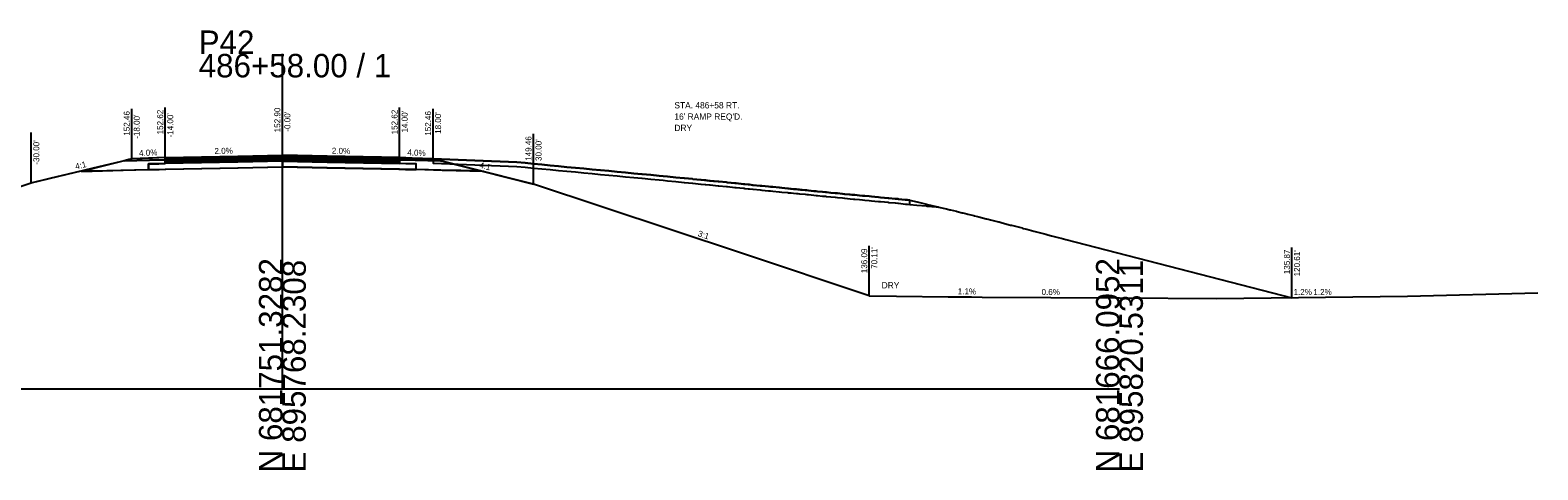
# Model space of a CAD drawing. Extents: x -26 to 4403, y -13 to 9578.
# Drawn here: x 3069.9 to 3250, y 8990.3 to 9042.8 of the extents above; entities that cross this region are included whole.
import ezdxf

# ---------------------------------------------------------------- set-up
doc = ezdxf.new("R2010")
doc.units = 0
for name, color, linetype in [('ASPHALT_19MM1', 7, 'Continuous'), ('ASPHALT_19MM2', 7, 'Continuous'), ('ASPHALT_9_5MM1', 7, 'Continuous'), ('CONST_LV3', 7, 'Continuous'), ('CONST_PROF_LV1', 7, 'Continuous'), ('Default', 7, 'Continuous'), ('DTM CONTOURS_MAJOR', 7, 'Continuous'), ('DTM_CONTOURS_MINOR', 7, 'Continuous'), ('DTM_P_FINISHED_GRADE', 7, 'Continuous'), ('DTM_X_BOUNDARY', 7, 'Continuous'), ('DTM_X_GROUND', 7, 'Continuous'), ('X_PROFILES_1', 7, 'Continuous'), ('XS_CELL', 7, 'Continuous'), ('XS_P_ASPHALT', 7, 'Continuous'), ('XS_P_CRUSHED_STONE', 7, 'Continuous'), ('XS_P_DR_ASPHALT', 7, 'Continuous'), ('XS_P_DR_ASPHALT_B', 7, 'Continuous'), ('XS_P_DR_GRAVEL', 7, 'Continuous'), ('XS_P_DRAINAGE', 7, 'Continuous'), ('XS_P_GROUND', 7, 'Continuous'), ('XS_P_SHOULDER', 7, 'Continuous'), ('XS_P_SUBGRADE_GRANULAR', 7, 'Continuous'), ('XS_P_TX_CLEARZONE', 7, 'Continuous'), ('XS_P_TX_FS_BS', 7, 'Continuous')]:
    doc.layers.add(name, color=color, linetype=linetype)

msp = doc.modelspace()

# ---------------------------------------------------------------- linework, layer by layer
at = {"layer": 'ASPHALT_19MM1'}
for points in [[(3094.67, 9027.5), (3100, 9027.61), (3100, 9027.54), (3100, 9027.42), (3094.67, 9027.32), (3086, 9027.14), (3086, 9027.26), (3086, 9027.33), (3094.67, 9027.5)], [(3105.33, 9027.5), (3100, 9027.61), (3100, 9027.54), (3100, 9027.42), (3105.33, 9027.32), (3114, 9027.14), (3114, 9027.26), (3114, 9027.33), (3105.33, 9027.5)]]:
    msp.add_lwpolyline(points, dxfattribs=at)
at = {"layer": 'ASPHALT_19MM2'}
for points in [[(3094.67, 9027.32), (3100, 9027.42), (3100, 9027.33), (3100, 9027.17), (3094.67, 9027.07), (3086, 9026.89), (3086, 9027.05), (3086, 9027.14), (3094.67, 9027.32)], [(3105.33, 9027.32), (3100, 9027.42), (3100, 9027.33), (3100, 9027.17), (3105.33, 9027.07), (3114, 9026.89), (3114, 9027.05), (3114, 9027.14), (3105.33, 9027.32)]]:
    msp.add_lwpolyline(points, dxfattribs=at)
at = {"layer": 'ASPHALT_9_5MM1'}
for points in [[(3094.67, 9027.79), (3100, 9027.9), (3100, 9027.85), (3100, 9027.78), (3094.67, 9027.67), (3086, 9027.5), (3086, 9027.57), (3086, 9027.62), (3094.67, 9027.79)], [(3105.33, 9027.79), (3100, 9027.9), (3100, 9027.85), (3100, 9027.78), (3105.33, 9027.67), (3114, 9027.5), (3114, 9027.57), (3114, 9027.62), (3105.33, 9027.79)]]:
    msp.add_lwpolyline(points, dxfattribs=at)
at = {"layer": 'CONST_LV3'}
for points in [[(3114, 9027.62), (3115, 9027.58), (3116, 9027.54), (3117, 9027.5), (3118, 9027.46), (3119, 9027.42), (3120, 9027.38), (3121, 9027.34), (3122, 9027.3), (3123, 9027.26), (3124, 9027.22), (3125, 9027.18), (3126, 9027.14), (3127, 9027.1), (3128, 9027.06), (3129, 9026.97), (3130, 9026.87), (3131, 9026.78), (3132, 9026.68), (3133, 9026.59), (3134, 9026.49), (3135, 9026.4), (3136, 9026.3), (3137, 9026.21), (3138, 9026.11), (3139, 9026.02), (3140, 9025.92), (3141, 9025.83), (3142, 9025.73), (3142.94, 9025.64), (3143, 9025.64), (3144, 9025.54), (3144, 9025.54), (3144, 9025.54), (3145, 9025.45), (3145, 9025.45), (3145, 9025.44), (3146, 9025.35), (3146, 9025.35), (3146.5, 9025.3), (3146.5, 9025.3), (3147, 9025.25), (3147.01, 9025.25), (3147.01, 9025.25), (3147.99, 9025.15), (3148.01, 9025.15), (3148.02, 9025.15), (3148.99, 9025.06), (3149.02, 9025.05), (3149.03, 9025.05), (3149.98, 9024.96), (3150.03, 9024.95), (3150.04, 9024.95), (3150.09, 9024.95), (3151.04, 9024.85), (3151.04, 9024.85), (3151.51, 9024.81), (3151.59, 9024.8), (3152.05, 9024.76), (3152.06, 9024.75), (3152.14, 9024.75), (3153.06, 9024.66), (3153.1, 9024.65), (3153.17, 9024.65), (3154.07, 9024.56), (3154.13, 9024.55), (3154.2, 9024.54), (3155.07, 9024.46), (3155.17, 9024.45), (3155.23, 9024.44), (3156.08, 9024.36), (3156.21, 9024.34), (3156.26, 9024.34), (3156.67, 9024.3), (3156.85, 9024.28), (3157.26, 9024.24), (3157.29, 9024.24), (3158.08, 9024.16), (3158.32, 9024.13), (3158.32, 9024.13), (3158.58, 9024.11), (3159.35, 9024.03), (3159.39, 9024.03), (3159.65, 9024), (3160.39, 9023.93), (3160.45, 9023.92), (3160.72, 9023.9), (3161.42, 9023.83), (3161.57, 9023.81), (3161.9, 9023.78), (3162.13, 9023.76), (3162.45, 9023.73), (3162.67, 9023.71), (3162.86, 9023.69), (3163.48, 9023.62), (3163.75, 9023.6), (3163.94, 9023.58), (3164.51, 9023.52), (3164.88, 9023.49), (3165.01, 9023.48), (3165.53, 9023.42), (3166.05, 9023.37), (3166.08, 9023.37), (3166.69, 9023.31), (3167.16, 9023.26), (3167.21, 9023.26), (3167.42, 9023.24), (3168.03, 9023.18), (3168.23, 9023.16), (3168.38, 9023.15), (3168.96, 9023.09), (3169.31, 9023.06), (3169.57, 9023.04), (3170.09, 9022.99), (3170.38, 9022.96), (3170.77, 9022.92), (3171.23, 9022.88), (3171.45, 9022.86), (3171.94, 9022.81), (3172.37, 9022.77), (3172.53, 9022.76), (3173.24, 9022.69), (3173.51, 9022.67), (3173.55, 9022.66), (3174.42, 9022.57), (3174.43, 9022.57), (3174.65, 9022.56), (3174.67, 9022.56), (3174.94, 9022.53)], [(3070, 9024.61), (3072.24, 9025.14), (3075.95, 9026.02)], [(3123.72, 9026.03), (3130, 9024.46)]]:
    msp.add_lwpolyline(points, dxfattribs=at)
at = {"layer": 'Default'}
for points in [[(3094.67, 9027.67), (3100, 9027.78), (3100, 9027.71), (3100, 9027.61), (3094.67, 9027.5), (3086, 9027.33), (3086, 9027.43), (3086, 9027.5), (3094.67, 9027.67)], [(3105.33, 9027.67), (3100, 9027.78), (3100, 9027.71), (3100, 9027.61), (3105.33, 9027.5), (3114, 9027.33), (3114, 9027.43), (3114, 9027.5), (3105.33, 9027.67)]]:
    msp.add_lwpolyline(points, dxfattribs=at)
at = {"layer": 'DTM_P_FINISHED_GRADE'}
for points in [[(3114, 9027.62), (3115, 9027.58), (3116, 9027.54), (3117, 9027.5), (3118, 9027.46)], [(3118, 9027.46), (3119, 9027.42), (3120, 9027.38), (3121, 9027.34), (3122, 9027.3), (3123, 9027.26), (3124, 9027.22), (3125, 9027.18), (3126, 9027.14), (3127, 9027.1), (3128, 9027.06), (3129, 9026.97), (3130, 9026.87), (3131, 9026.78), (3132, 9026.68), (3133, 9026.59), (3134, 9026.49), (3135, 9026.4), (3136, 9026.3), (3137, 9026.21), (3138, 9026.11), (3139, 9026.02), (3140, 9025.92), (3141, 9025.83), (3142, 9025.73), (3142.94, 9025.64), (3143, 9025.64), (3144, 9025.54), (3144, 9025.54), (3144, 9025.54), (3145, 9025.45), (3145, 9025.45), (3145.5, 9025.4), (3145.5, 9025.4), (3146, 9025.35), (3146, 9025.35), (3146.01, 9025.35), (3147, 9025.25), (3147.01, 9025.25), (3147.01, 9025.25), (3147.99, 9025.15), (3148.01, 9025.15), (3148.02, 9025.15), (3148.99, 9025.06), (3149.02, 9025.05), (3149.03, 9025.05), (3149.98, 9024.96), (3150.03, 9024.95), (3150.04, 9024.95), (3150.51, 9024.91), (3150.57, 9024.9), (3151.04, 9024.85), (3151.04, 9024.85), (3151.11, 9024.85), (3152.05, 9024.76), (3152.06, 9024.75), (3152.14, 9024.75), (3153.06, 9024.66), (3153.1, 9024.65), (3153.17, 9024.65), (3154.07, 9024.56), (3154.13, 9024.55), (3154.2, 9024.54), (3155.07, 9024.46), (3155.17, 9024.45), (3155.23, 9024.44), (3155.66, 9024.4), (3155.79, 9024.39), (3156.21, 9024.34), (3156.26, 9024.34), (3157.08, 9024.26), (3157.26, 9024.24), (3157.29, 9024.24), (3158.08, 9024.16), (3158.32, 9024.13), (3158.32, 9024.13), (3158.58, 9024.11), (3159.35, 9024.03), (3159.39, 9024.03), (3159.65, 9024), (3160.39, 9023.93), (3160.45, 9023.92), (3160.8, 9023.89), (3161.07, 9023.86), (3161.42, 9023.83), (3161.57, 9023.81), (3161.79, 9023.79), (3162.45, 9023.73), (3162.67, 9023.71), (3162.86, 9023.69), (3163.48, 9023.62), (3163.75, 9023.6), (3163.94, 9023.58), (3164.51, 9023.52), (3164.88, 9023.49), (3165.01, 9023.48), (3165.53, 9023.42), (3166.05, 9023.37), (3166.08, 9023.37), (3166.33, 9023.35), (3166.93, 9023.29), (3167.16, 9023.26), (3167.21, 9023.26), (3167.83, 9023.2), (3168.23, 9023.16), (3168.38, 9023.15), (3168.96, 9023.09), (3169.31, 9023.06), (3169.57, 9023.04), (3170.09, 9022.99), (3170.38, 9022.96), (3170.77, 9022.92), (3171.23, 9022.88), (3171.45, 9022.86), (3171.94, 9022.81), (3172.37, 9022.77), (3172.45, 9022.76), (3173.19, 9022.69), (3173.24, 9022.69), (3173.51, 9022.67), (3173.6, 9022.66), (3174.43, 9022.57), (3174.65, 9022.56), (3174.67, 9022.56), (3174.94, 9022.53)]]:
    msp.add_lwpolyline(points, dxfattribs=at)
at = {"layer": 'DTM_X_GROUND'}
for points in [[(3200, 9010.84), (3211.61, 9010.77), (3234.42, 9011.04), (3249.98, 9011.47)], [(3170.11, 9011.09), (3173.36, 9011.06), (3179.52, 9010.99), (3182.34, 9010.96), (3183.61, 9010.95), (3200, 9010.84)]]:
    msp.add_lwpolyline(points, dxfattribs=at)
at = {"layer": 'XS_CELL'}
for p, q in [((3100, 9000), (3100, 9040)), ((3000, 9000), (3100, 9000)), ((3100, 9000), (3200, 9000))]:
    msp.add_line(p, q, dxfattribs=at)
at = {"layer": 'XS_P_ASPHALT'}
msp.add_lwpolyline([(3094.67, 9027.79), (3100, 9027.9), (3105.33, 9027.79), (3114, 9027.62), (3114, 9027.34), (3114, 9026.89), (3105.33, 9027.07), (3100, 9027.17), (3094.67, 9027.07), (3086, 9026.89), (3086, 9027.34), (3086, 9027.62), (3094.67, 9027.79)], dxfattribs=at)
at = {"layer": 'XS_P_CRUSHED_STONE'}
for points in [[(3084.48, 9027.56), (3082, 9027.46), (3081.66, 9027.38), (3081.11, 9027.24), (3084.14, 9027.29), (3086, 9027.33), (3086, 9027.51), (3086, 9027.62), (3084.48, 9027.56)], [(3115.52, 9027.56), (3114, 9027.62), (3114, 9027.51), (3114, 9027.33), (3115.86, 9027.29), (3118.89, 9027.24), (3118.34, 9027.38), (3118, 9027.46), (3115.52, 9027.56)], [(3085.29, 9026.21), (3086.08, 9026.23), (3094.7, 9026.4), (3100, 9026.51), (3100, 9026.92), (3100, 9027.17), (3094.67, 9027.07), (3086, 9026.89), (3085.24, 9026.88), (3084.01, 9026.86), (3084.01, 9026.61), (3084, 9026.19), (3085.29, 9026.21)], [(3114.71, 9026.21), (3116, 9026.19), (3115.99, 9026.61), (3115.99, 9026.86), (3114.76, 9026.88), (3114, 9026.89), (3105.33, 9027.07), (3100, 9027.17), (3100, 9026.92), (3100, 9026.51), (3105.3, 9026.4), (3113.92, 9026.23), (3114.71, 9026.21)]]:
    msp.add_lwpolyline(points, dxfattribs=at)
at = {"layer": 'XS_P_DR_ASPHALT'}
msp.add_lwpolyline([(3116, 9027.54), (3117, 9027.5), (3118, 9027.46), (3118, 9027.34), (3117, 9027.38), (3116, 9027.42), (3115, 9027.46), (3114, 9027.5), (3114, 9027.62), (3115, 9027.58), (3116, 9027.54)], dxfattribs=at)
at = {"layer": 'XS_P_DR_ASPHALT_B'}
msp.add_lwpolyline([(3116, 9027.42), (3117, 9027.38), (3118, 9027.34), (3118, 9027.21), (3117, 9027.25), (3116, 9027.29), (3115, 9027.33), (3114, 9027.37), (3114, 9027.5), (3115, 9027.46), (3116, 9027.42)], dxfattribs=at)
at = {"layer": 'XS_P_DR_GRAVEL'}
for points in [[(3122, 9027.3), (3121, 9027.34), (3120, 9027.38), (3119, 9027.42), (3118, 9027.46), (3118, 9026.96), (3119, 9026.92), (3120, 9026.88), (3121, 9026.84), (3122, 9026.8), (3123, 9026.76), (3124, 9026.72), (3125, 9026.68), (3126, 9026.64), (3127, 9026.6), (3128, 9026.56), (3129, 9026.47), (3130, 9026.37), (3131, 9026.28), (3132, 9026.18), (3133, 9026.09), (3134, 9025.99), (3135, 9025.9), (3136, 9025.8), (3137, 9025.71), (3138, 9025.61), (3139, 9025.52), (3140, 9025.42), (3141, 9025.33), (3142, 9025.23), (3142.94, 9025.14), (3142.94, 9025.14), (3143, 9025.14), (3143, 9025.14), (3143, 9025.14), (3144, 9025.04), (3144, 9025.04), (3144, 9025.04), (3145, 9024.95), (3145, 9024.95), (3145.5, 9024.9), (3145.5, 9024.9), (3146, 9024.85), (3146, 9024.85), (3146.01, 9024.85), (3147, 9024.75), (3147.01, 9024.75), (3147.01, 9024.75), (3147.99, 9024.65), (3148.01, 9024.65), (3148.02, 9024.65), (3148.99, 9024.56), (3149.02, 9024.55), (3149.03, 9024.55), (3149.98, 9024.46), (3150.03, 9024.45), (3150.04, 9024.45), (3150.51, 9024.41), (3150.57, 9024.4), (3151.04, 9024.35), (3151.04, 9024.35), (3151.11, 9024.35), (3152.05, 9024.26), (3152.06, 9024.25), (3152.14, 9024.25), (3153.06, 9024.16), (3153.1, 9024.15), (3153.17, 9024.15), (3154.07, 9024.06), (3154.13, 9024.05), (3154.2, 9024.04), (3155.07, 9023.96), (3155.17, 9023.95), (3155.23, 9023.94), (3155.66, 9023.9), (3155.79, 9023.89), (3156.21, 9023.84), (3156.26, 9023.84), (3157.08, 9023.76), (3157.26, 9023.74), (3157.29, 9023.74), (3158.08, 9023.66), (3158.32, 9023.63), (3158.32, 9023.63), (3158.58, 9023.61), (3159.35, 9023.53), (3159.39, 9023.53), (3159.65, 9023.5), (3160.39, 9023.43), (3160.45, 9023.42), (3160.8, 9023.39), (3161.07, 9023.36), (3161.42, 9023.33), (3161.57, 9023.31), (3161.79, 9023.29), (3162.45, 9023.23), (3162.67, 9023.21), (3162.86, 9023.19), (3163.48, 9023.12), (3163.75, 9023.1), (3163.94, 9023.08), (3164.51, 9023.02), (3164.88, 9022.99), (3165.01, 9022.98), (3165.53, 9022.92), (3166.05, 9022.87), (3166.08, 9022.87), (3166.33, 9022.85), (3166.93, 9022.79), (3167.16, 9022.76), (3167.21, 9022.76), (3167.83, 9022.7), (3168.23, 9022.66), (3168.38, 9022.65), (3168.96, 9022.59), (3169.31, 9022.56), (3169.57, 9022.54), (3170.09, 9022.49), (3170.38, 9022.46), (3170.77, 9022.42), (3171.23, 9022.38), (3171.45, 9022.36), (3171.94, 9022.31), (3172.37, 9022.27), (3172.45, 9022.26), (3173.19, 9022.19), (3173.24, 9022.19), (3173.51, 9022.17), (3173.6, 9022.16), (3174.43, 9022.07), (3174.65, 9022.06), (3174.67, 9022.06), (3174.94, 9022.03), (3174.94, 9022.53), (3174.67, 9022.56), (3174.65, 9022.56), (3174.43, 9022.57), (3173.6, 9022.66), (3173.51, 9022.67), (3173.24, 9022.69), (3173.19, 9022.69), (3172.45, 9022.76), (3172.37, 9022.77), (3171.94, 9022.81), (3171.45, 9022.86), (3171.23, 9022.88), (3170.77, 9022.92), (3170.38, 9022.96), (3170.09, 9022.99), (3169.57, 9023.04), (3169.31, 9023.06), (3168.96, 9023.09), (3168.38, 9023.15), (3168.23, 9023.16), (3167.83, 9023.2), (3167.21, 9023.26), (3167.16, 9023.26), (3166.93, 9023.29), (3166.33, 9023.35), (3166.08, 9023.37), (3166.05, 9023.37), (3165.53, 9023.42), (3165.01, 9023.48), (3164.88, 9023.49), (3164.51, 9023.52), (3163.94, 9023.58), (3163.75, 9023.6), (3163.48, 9023.62), (3162.86, 9023.69), (3162.67, 9023.71), (3162.45, 9023.73), (3161.79, 9023.79), (3161.57, 9023.81), (3161.42, 9023.83), (3161.07, 9023.86), (3160.8, 9023.89), (3160.45, 9023.92), (3160.39, 9023.93), (3159.65, 9024), (3159.39, 9024.03), (3159.35, 9024.03), (3158.58, 9024.11), (3158.32, 9024.13), (3158.32, 9024.13), (3158.08, 9024.16), (3157.29, 9024.24), (3157.26, 9024.24), (3157.08, 9024.26), (3156.26, 9024.34), (3156.21, 9024.34), (3155.79, 9024.39), (3155.66, 9024.4), (3155.23, 9024.44), (3155.17, 9024.45), (3155.07, 9024.46), (3154.2, 9024.54), (3154.13, 9024.55), (3154.07, 9024.56), (3153.17, 9024.65), (3153.1, 9024.65), (3153.06, 9024.66), (3152.14, 9024.75), (3152.06, 9024.75), (3152.05, 9024.76), (3151.11, 9024.85), (3151.04, 9024.85), (3151.04, 9024.85), (3150.57, 9024.9), (3150.51, 9024.91), (3150.04, 9024.95), (3150.03, 9024.95), (3149.98, 9024.96), (3149.03, 9025.05), (3149.02, 9025.05), (3148.99, 9025.06), (3148.02, 9025.15), (3148.01, 9025.15), (3147.99, 9025.15), (3147.01, 9025.25), (3147.01, 9025.25), (3147, 9025.25), (3146.01, 9025.35), (3146, 9025.35), (3146, 9025.35), (3145.5, 9025.4), (3145.5, 9025.4), (3145, 9025.45), (3145, 9025.45), (3144, 9025.54), (3144, 9025.54), (3144, 9025.54), (3143, 9025.64), (3143, 9025.64), (3143, 9025.64), (3142.94, 9025.64), (3142.94, 9025.64), (3142, 9025.73), (3141, 9025.83), (3140, 9025.92), (3139, 9026.02), (3138, 9026.11), (3137, 9026.21), (3136, 9026.3), (3135, 9026.4), (3134, 9026.49), (3133, 9026.59), (3132, 9026.68), (3131, 9026.78), (3130, 9026.87), (3129, 9026.97), (3128, 9027.06), (3127, 9027.1), (3126, 9027.14), (3125, 9027.18), (3124, 9027.22), (3123, 9027.26), (3122, 9027.3)], [(3174.94, 9022.03), (3175.79, 9021.95), (3175.8, 9021.95), (3176.94, 9021.84), (3177.03, 9021.83), (3178.12, 9021.73), (3178.37, 9021.71), (3178.42, 9021.7)]]:
    msp.add_lwpolyline(points, dxfattribs=at)
at = {"layer": 'XS_P_GROUND'}
for points in [[(3042.68, 9015.51), (3053.11, 9018.98), (3070, 9024.61), (3077.43, 9026.39), (3082, 9027.46)], [(3170.11, 9011.09), (3154.85, 9016.18), (3130, 9024.46), (3122.57, 9026.32), (3118, 9027.46)], [(3174.94, 9022.53), (3175.79, 9022.33), (3175.8, 9022.33), (3175.8, 9022.33), (3175.82, 9022.33), (3176.94, 9022.06), (3176.95, 9022.06), (3177.03, 9022.04), (3177.08, 9022.03), (3178.12, 9021.78), (3178.13, 9021.78), (3178.37, 9021.72), (3178.44, 9021.7), (3179.31, 9021.49), (3179.35, 9021.48), (3179.73, 9021.39), (3179.81, 9021.37), (3180.53, 9021.2), (3180.61, 9021.18), (3181.2, 9021.03), (3181.28, 9021.02), (3181.77, 9020.89), (3181.9, 9020.86), (3182.62, 9020.68), (3182.69, 9020.66), (3183.04, 9020.58), (3183.22, 9020.53), (3184.08, 9020.31), (3184.13, 9020.3), (3184.33, 9020.26), (3184.59, 9020.19), (3185.56, 9019.94), (3185.62, 9019.92), (3185.64, 9019.92), (3185.97, 9019.84), (3186.98, 9019.56), (3187.01, 9019.56), (3187.09, 9019.54), (3187.44, 9019.46), (3188.36, 9019.21), (3188.42, 9019.19), (3188.55, 9019.16), (3188.93, 9019.06), (3189.76, 9018.84), (3189.92, 9018.8), (3190.25, 9018.71), (3190.58, 9018.63), (3191.2, 9018.46), (3191.45, 9018.4), (3191.89, 9018.28), (3192.19, 9018.2), (3192.67, 9018.07), (3193.04, 9017.97), (3193.58, 9017.82), (3220.61, 9010.87)]]:
    msp.add_lwpolyline(points, dxfattribs=at)
at = {"layer": 'XS_P_SHOULDER'}
for points in [[(3086, 9027.62), (3082, 9027.46)], [(3114, 9027.62), (3118, 9027.46)]]:
    msp.add_lwpolyline(points, dxfattribs=at)
at = {"layer": 'XS_P_SUBGRADE_GRANULAR'}
for points in [[(3075.95, 9026.02), (3079.04, 9026.09), (3084, 9026.19), (3085.24, 9026.21), (3086, 9026.23)], [(3086, 9027.16), (3086, 9027.33), (3084.14, 9027.29), (3081.11, 9027.24), (3079.18, 9026.76), (3076.05, 9025.97), (3080.98, 9026.1), (3084, 9026.19), (3084.01, 9026.61), (3084.01, 9026.86), (3085.24, 9026.88), (3086, 9026.89), (3086, 9027.16)], [(3086, 9026.23), (3094.67, 9026.4), (3100, 9026.51)], [(3114, 9026.23), (3105.33, 9026.4), (3100, 9026.51)], [(3114, 9027.16), (3114, 9027.33), (3115.86, 9027.29), (3118.89, 9027.24), (3120.86, 9026.75), (3124.06, 9025.95), (3119.07, 9026.09), (3116, 9026.19), (3115.99, 9026.61), (3115.99, 9026.86), (3114.76, 9026.88), (3114, 9026.89), (3114, 9027.16)], [(3123.72, 9026.03), (3118.94, 9026.13), (3116, 9026.19), (3114.76, 9026.21), (3114, 9026.23)]]:
    msp.add_lwpolyline(points, dxfattribs=at)
at = {"layer": 'XS_P_TX_CLEARZONE'}
for p, q in [((3082, 9027.46), (3082, 9033.46)), ((3086, 9027.62), (3086, 9033.62)), ((3100, 9027.9), (3100, 9033.9)), ((3114, 9027.62), (3114, 9033.62)), ((3118, 9027.46), (3118, 9033.46)), ((3070, 9024.61), (3070, 9030.61)), ((3070, 9024.61), (3070, 9030.61)), ((3130, 9024.46), (3130, 9030.46)), ((3130, 9024.46), (3130, 9030.46)), ((3170.11, 9011.09), (3170.11, 9017.09)), ((3170.11, 9011.09), (3170.11, 9017.09)), ((3220.61, 9010.87), (3220.61, 9016.87))]:
    msp.add_line(p, q, dxfattribs=at)

# ---------------------------------------------------------------- texts
at = {"layer": 'CONST_PROF_LV1'}
for p in [(3069.96, 9024.55), (3129.96, 9024.4)]:
    msp.add_text('X', height=0.12, dxfattribs=at).set_placement(p)
at = {"layer": 'Default'}
for p in [(3069.96, 9024.55), (3129.96, 9024.4)]:
    msp.add_text('X', height=0.12, dxfattribs=at).set_placement(p)
at = {"layer": 'DTM CONTOURS_MAJOR'}
for p in [(3085.96, 9027.56), (3099.96, 9027.84), (3113.96, 9027.56)]:
    msp.add_text('X', height=0.12, dxfattribs=at).set_placement(p)
at = {"layer": 'DTM_CONTOURS_MINOR'}
msp.add_text('X', height=0.12, dxfattribs=at).set_placement((3170.07, 9011.03))
at = {"layer": 'DTM_X_BOUNDARY'}
for p in [(3081.96, 9027.4), (3117.96, 9027.4)]:
    msp.add_text('X', height=0.12, dxfattribs=at).set_placement(p)
at = {"layer": 'X_PROFILES_1'}
for p in [(3170.07, 9011.03), (3220.57, 9010.81)]:
    msp.add_text('X', height=0.12, dxfattribs=at).set_placement(p)
at = {"layer": 'XS_CELL'}
for s, p in [('P42', (3090, 9040)), ('486+58.00 / 1', (3090, 9037.2))]:
    msp.add_text(s, height=2.8, dxfattribs=at).set_placement(p)
for s, p in [('N 681751.3282', (3100, 8990)), ('E 895768.2308', (3102.8, 8990)), ('N 681666.0952', (3200, 8990)), ('E 895820.5311', (3202.8, 8990))]:
    msp.add_text(s, height=2.8, rotation=90, dxfattribs=at).set_placement(p)
at = {"layer": 'XS_P_DRAINAGE'}
for s, p in [('STA. 486+58 RT.', (3146.83, 9033.49)), ("16' RAMP REQ'D.", (3146.83, 9032.14)), ('DRY', (3146.83, 9030.79)), ('DRY', (3171.59, 9011.99))]:
    msp.add_text(s, height=0.75, dxfattribs=at).set_placement(p)
at = {"layer": 'XS_P_TX_CLEARZONE'}
for s, p in [('152.46', (3081.76, 9030.23)), ('152.62', (3085.76, 9030.39)), ("-14.00'", (3086.96, 9030.02)), ('152.90', (3099.76, 9030.64)), ("-0.00'", (3100.96, 9030.71)), ('152.62', (3113.76, 9030.39)), ("14.00'", (3114.96, 9030.61)), ('152.46', (3117.76, 9030.23)), ("18.00'", (3118.96, 9030.45)), ("-18.00'", (3082.96, 9029.86)), ("-30.00'", (3070.96, 9026.77)), ("-30.00'", (3070.96, 9026.77)), ('149.46', (3129.76, 9027.23)), ('149.46', (3129.76, 9027.23)), ("30.00'", (3130.96, 9027.21)), ("30.00'", (3130.96, 9027.21)), ('136.09', (3169.87, 9013.8)), ('136.09', (3169.87, 9013.8)), ("70.11'", (3171.07, 9014.32)), ("70.11'", (3171.07, 9014.32)), ('135.87', (3220.37, 9013.68)), ("120.61'", (3221.57, 9013.42))]:
    msp.add_text(s, height=0.72, rotation=90, dxfattribs=at).set_placement(p)
at = {"layer": 'XS_P_TX_FS_BS'}
for s, rotation, p in [('4.0%', 2.2906, (3082.89, 9027.8)), ('2.0%', 1.1458, (3091.89, 9028.04)), ('2.0%', 358.8542, (3105.9, 9028.08)), ('4.0%', 357.7094, (3114.91, 9027.88)), ('4:1', 13.3539, (3075.34, 9026.19)), ('4:1', 345.9638, (3123.48, 9026.4)), ('3:1', 341.5668, (3149.57, 9018.25)), ('1.1%', 359.3939, (3180.68, 9011.28)), ('1.1%', 359.3939, (3180.68, 9011.28)), ('0.6%', 359.6329, (3190.69, 9011.2)), ('0.6%', 359.6329, (3190.69, 9011.2)), ('1.2%', 0.672, (3220.8, 9011.18)), ('1.2%', 0.672, (3223.17, 9011.18))]:
    msp.add_text(s, height=0.72, rotation=rotation, dxfattribs=at).set_placement(p)

doc.saveas('drawing.dxf')
